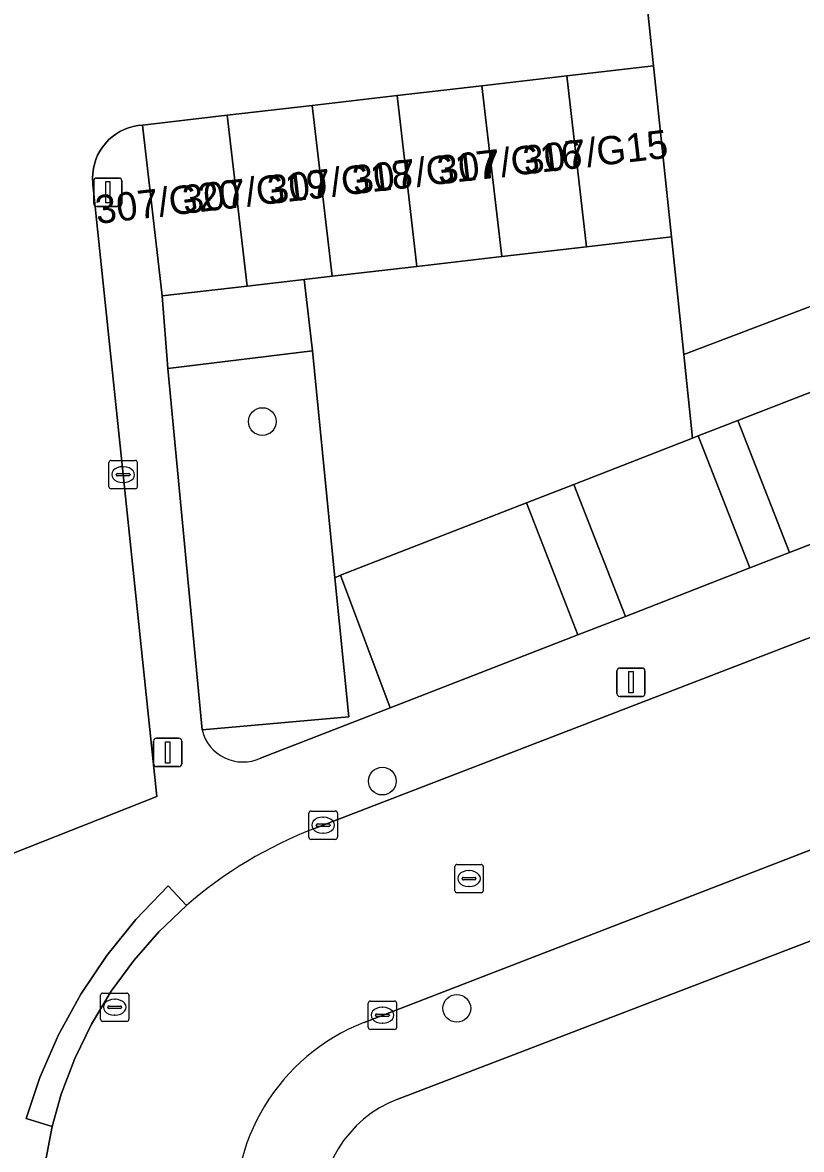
# Model space of a CAD drawing. Extents: x 161248 to 161848, y 384871 to 385383.
# Drawn here: x 161318.63 to 161346.09, y 385275.64 to 385315.39 of the extents above; entities that cross this region are included whole.
import ezdxf

# ---------------------------------------------------------------- set-up
doc = ezdxf.new("R2010")
doc.units = 0
for name, color, linetype in [('IMGEO_Boom', 7, 'Continuous'), ('IMGEO_Erf', 7, 'Continuous'), ('IMGEO_Groenvoorziening', 7, 'Continuous'), ('IMGEO_Kolk', 7, 'Continuous'), ('IMGEO_Lichtmast', 7, 'Continuous'), ('IMGEO_Pand', 7, 'Continuous'), ('IMGEO_Pand_nummerreeks', 7, 'Continuous'), ('IMGEO_Parkeervlak_open', 7, 'Continuous'), ('IMGEO_Rijbaan_lokaal_open', 7, 'Continuous'), ('IMGEO_Rioolput', 7, 'Continuous'), ('IMGEO_Voetpad_open', 7, 'Continuous')]:
    doc.layers.add(name, color=color, linetype=linetype)

msp = doc.modelspace()

# ---------------------------------------------------------------- linework, layer by layer
at = {"layer": 'IMGEO_Boom'}
for centre in [(161327.085, 385301.316), (161331.313, 385288.635), (161333.94, 385280.622)]:
    msp.add_circle(centre, 0.489, dxfattribs=at)
at = {"layer": 'IMGEO_Erf'}
for points in [[(161359.136, 385309.338), (161359.113, 385309.131), (161357.21, 385308.445), (161357.263, 385308.334), (161353.721, 385306.981), (161353.329, 385308.005), (161341.943, 385303.675), (161342.253, 385300.73), (161342.45, 385300.807), (161343.848, 385301.35), (161352.373, 385304.672), (161354.992, 385305.692), (161355.731, 385305.973), (161364.421, 385309.284), (161365.542, 385309.711), (161370.74, 385311.66), (161371.446, 385311.929), (161363.214, 385333.159)], [(161329.169, 385273.002), (161331.681, 385250), (161333.41, 385234.163), (161333.427, 385234.012), (161340.373, 385234.791), (161340.358, 385234.928), (161342.384, 385235.15), (161341.728, 385241.128), (161339.689, 385240.904), (161338.691, 385250), (161338.032, 385256.004), (161341.905, 385256.429), (161341.47, 385260.388), (161341.19, 385260.358), (161340.033, 385270.899), (161354.412, 385272.477), (161354.279, 385273.691), (161354.916, 385273.761), (161354.019, 385285.915), (161331.859, 385277.42)]]:
    msp.add_lwpolyline(points, dxfattribs=at)
msp.add_arc((161333.382, 385273.465), 4.239, 111.0615, 186.2663, dxfattribs=at)
at = {"layer": 'IMGEO_Groenvoorziening'}
msp.add_lwpolyline([(161341.943, 385303.675), (161341.506, 385307.829), (161338.515, 385307.482), (161335.523, 385307.135), (161332.532, 385306.788), (161329.54, 385306.441), (161328.561, 385306.327), (161328.853, 385303.808), (161329.644, 385295.807), (161329.842, 385295.895), (161336.393, 385298.447), (161338.07, 385299.1), (161342.253, 385300.73)], close=True, dxfattribs=at)
at = {"layer": 'IMGEO_Kolk'}
for p, q in [((161321.752, 385299.943), (161322.604, 385299.943)), ((161321.677, 385299.017), (161321.677, 385299.869)), ((161321.979, 385299.486), (161322.377, 385299.486)), ((161322.165, 385299.723), (161322.19, 385299.723)), ((161322.678, 385299.869), (161322.678, 385299.017)), ((161321.936, 385299.437), (161321.936, 385299.449)), ((161322.374, 385299.4), (161321.976, 385299.4)), ((161322.188, 385299.163), (161322.163, 385299.163)), ((161322.42, 385299.449), (161322.42, 385299.437)), ((161322.604, 385298.943), (161321.752, 385298.943)), ((161328.802, 385287.58), (161329.654, 385287.58)), ((161328.727, 385286.654), (161328.727, 385287.506)), ((161329.215, 385287.36), (161329.24, 385287.36)), ((161329.728, 385287.506), (161329.728, 385286.654)), ((161328.986, 385287.074), (161328.986, 385287.086)), ((161329.424, 385287.037), (161329.026, 385287.037)), ((161329.029, 385287.123), (161329.427, 385287.123)), ((161329.238, 385286.8), (161329.213, 385286.8)), ((161329.47, 385287.086), (161329.47, 385287.074)), ((161329.654, 385286.58), (161328.802, 385286.58)), ((161330.818, 385279.952), (161330.818, 385280.804)), ((161330.893, 385280.878), (161331.745, 385280.878)), ((161331.819, 385280.804), (161331.819, 385279.952)), ((161331.12, 385280.421), (161331.518, 385280.421)), ((161331.306, 385280.658), (161331.331, 385280.658)), ((161331.077, 385280.372), (161331.077, 385280.384)), ((161331.515, 385280.335), (161331.117, 385280.335)), ((161331.329, 385280.098), (161331.304, 385280.098)), ((161331.561, 385280.384), (161331.561, 385280.372)), ((161331.745, 385279.878), (161330.893, 385279.878))]:
    msp.add_line(p, q, dxfattribs=at)
for points in [[(161321.752, 385299.943), (161322.604, 385299.943)], [(161321.677, 385299.017), (161321.677, 385299.869)], [(161322.678, 385299.869), (161322.678, 385299.017)], [(161322.604, 385298.943), (161321.752, 385298.943)], [(161328.802, 385287.58), (161329.654, 385287.58)], [(161328.727, 385286.654), (161328.727, 385287.506)], [(161329.728, 385287.506), (161329.728, 385286.654)], [(161329.654, 385286.58), (161328.802, 385286.58)], [(161330.818, 385279.952), (161330.818, 385280.804)], [(161330.893, 385280.878), (161331.745, 385280.878)], [(161331.819, 385280.804), (161331.819, 385279.952)], [(161331.745, 385279.878), (161330.893, 385279.878)]]:
    msp.add_lwpolyline(points, dxfattribs=at)
for centre, radius, start, end in [((161321.754, 385299.867), 0.0765, 91.552, 178.448), ((161321.754, 385299.867), 0.0765, 91.552, 178.448), ((161322.602, 385299.867), 0.0765, 1.552, 88.448), ((161322.602, 385299.867), 0.0765, 1.552, 88.448), ((161321.976, 385299.446), 0.0403, 85.8775, 175.7526), ((161322.381, 385299.448), 0.0386, 1.7309, 96.639), ((161321.973, 385299.436), 0.0366, 178.938, 274.7102), ((161322.377, 385299.443), 0.043, 264.8664, 352.4533), ((161321.754, 385299.019), 0.0765, 181.552, 268.448), ((161321.754, 385299.019), 0.0765, 181.552, 268.448), ((161322.602, 385299.019), 0.0765, 271.552, 358.448), ((161322.602, 385299.019), 0.0765, 271.552, 358.448), ((161328.804, 385287.504), 0.0765, 91.552, 178.448), ((161328.804, 385287.504), 0.0765, 91.552, 178.448), ((161329.652, 385287.504), 0.0765, 1.552, 88.448), ((161329.652, 385287.504), 0.0765, 1.552, 88.448), ((161329.026, 385287.083), 0.0403, 85.8775, 175.7526), ((161329.023, 385287.073), 0.0366, 178.938, 274.7102), ((161329.427, 385287.08), 0.043, 264.8664, 352.4533), ((161329.431, 385287.085), 0.0386, 1.7309, 96.639), ((161328.804, 385286.656), 0.0765, 181.552, 268.448), ((161328.804, 385286.656), 0.0765, 181.552, 268.448), ((161329.652, 385286.656), 0.0765, 271.552, 358.448), ((161329.652, 385286.656), 0.0765, 271.552, 358.448), ((161330.895, 385280.802), 0.0765, 91.552, 178.448), ((161330.895, 385280.802), 0.0765, 91.552, 178.448), ((161331.743, 385280.802), 0.0765, 1.552, 88.448), ((161331.743, 385280.802), 0.0765, 1.552, 88.448), ((161331.117, 385280.381), 0.0403, 85.8775, 175.7526), ((161331.522, 385280.383), 0.0386, 1.7309, 96.639), ((161331.114, 385280.371), 0.0366, 178.938, 274.7102), ((161331.518, 385280.378), 0.043, 264.8664, 352.4533), ((161330.895, 385279.954), 0.0765, 181.552, 268.448), ((161330.895, 385279.954), 0.0765, 181.552, 268.448), ((161331.743, 385279.954), 0.0765, 271.552, 358.448), ((161331.743, 385279.954), 0.0765, 271.552, 358.448)]:
    msp.add_arc(centre, radius, start, end, dxfattribs=at)
for centre, major_axis, ratio, start_param, end_param in [((161322.164, 385299.443), (-0.387, 0.002), 0.722429, 4.712389, 7.853982), ((161322.189, 385299.443), (-0.39, 0.002), 0.717154, 1.570796, 4.712389), ((161329.214, 385287.08), (-0.387, 0.002), 0.722429, 4.712389, 7.853982), ((161329.239, 385287.08), (-0.39, 0.002), 0.717154, 1.570796, 4.712389), ((161331.305, 385280.378), (-0.387, 0.002), 0.722429, 4.712389, 7.853982), ((161331.33, 385280.378), (-0.39, 0.002), 0.717154, 1.570796, 4.712389)]:
    msp.add_ellipse(centre, major_axis=major_axis, ratio=ratio, start_param=start_param, end_param=end_param, dxfattribs=at)
at = {"layer": 'IMGEO_Lichtmast'}
for p, q in [((161321.242, 385309.905), (161322.032, 385309.905)), ((161322.032, 385309.905), (161321.242, 385309.905)), ((161321.142, 385309.005), (161321.142, 385309.805)), ((161321.142, 385309.805), (161321.142, 385309.005)), ((161322.132, 385309.805), (161322.132, 385309.005)), ((161322.132, 385309.005), (161322.132, 385309.805)), ((161322.032, 385308.905), (161321.242, 385308.905)), ((161321.242, 385308.905), (161322.032, 385308.905)), ((161339.581, 385291.722), (161339.581, 385292.522)), ((161339.581, 385292.522), (161339.581, 385291.722)), ((161339.681, 385292.622), (161340.471, 385292.622)), ((161340.471, 385292.622), (161339.681, 385292.622)), ((161340.571, 385292.522), (161340.571, 385291.722)), ((161340.571, 385291.722), (161340.571, 385292.522)), ((161340.471, 385291.622), (161339.681, 385291.622)), ((161339.681, 385291.622), (161340.471, 385291.622)), ((161323.252, 385289.248), (161323.252, 385290.048)), ((161323.252, 385290.048), (161323.252, 385289.248)), ((161323.352, 385290.148), (161324.142, 385290.148)), ((161324.142, 385290.148), (161323.352, 385290.148)), ((161324.242, 385290.048), (161324.242, 385289.248)), ((161324.242, 385289.248), (161324.242, 385290.048)), ((161324.142, 385289.148), (161323.352, 385289.148)), ((161323.352, 385289.148), (161324.142, 385289.148))]:
    msp.add_line(p, q, dxfattribs=at)
for points in [[(161321.562, 385309.78), (161321.712, 385309.78), (161321.712, 385309.03), (161321.562, 385309.03), (161321.562, 385309.78)], [(161340.001, 385292.497), (161340.151, 385292.497), (161340.151, 385291.747), (161340.001, 385291.747), (161340.001, 385292.497)], [(161323.672, 385290.023), (161323.822, 385290.023), (161323.822, 385289.273), (161323.672, 385289.273), (161323.672, 385290.023)]]:
    msp.add_lwpolyline(points, dxfattribs=at)
for centre, start, end in [((161321.242, 385309.805), 90, 180), ((161321.242, 385309.805), 90, 180), ((161322.032, 385309.805), 0, 90), ((161322.032, 385309.805), 360, 90), ((161321.242, 385309.005), 180, 270), ((161321.242, 385309.005), 180, 270), ((161322.032, 385309.005), 270, 0), ((161322.032, 385309.005), 270, 0), ((161339.681, 385292.522), 90, 180), ((161339.681, 385292.522), 90, 180), ((161340.471, 385292.522), 0, 90), ((161340.471, 385292.522), 360, 90), ((161339.681, 385291.722), 180, 270), ((161339.681, 385291.722), 180, 270), ((161340.471, 385291.722), 270, 0), ((161340.471, 385291.722), 270, 0), ((161323.352, 385290.048), 90, 180), ((161323.352, 385290.048), 90, 180), ((161324.142, 385290.048), 0, 90), ((161324.142, 385290.048), 360, 90), ((161323.352, 385289.248), 180, 270), ((161323.352, 385289.248), 180, 270), ((161324.142, 385289.248), 270, 0), ((161324.142, 385289.248), 270, 0)]:
    msp.add_arc(centre, 0.1, start, end, dxfattribs=at)
at = {"layer": 'IMGEO_Pand'}
msp.add_lwpolyline([(161364.248, 385315.991), (161365.668, 385316.057), (161365.156, 385326.33), (161363.758, 385326.266), (161363.523, 385331.042), (161339.195, 385329.807), (161339.824, 385323.814), (161340.871, 385313.86), (161341.506, 385307.829), (161341.943, 385303.675), (161353.329, 385308.005), (161353.721, 385306.981), (161357.263, 385308.334), (161357.21, 385308.445), (161359.113, 385309.131), (161359.136, 385309.338)], dxfattribs=at)
for points in [[(161338.515, 385307.482), (161341.506, 385307.829), (161340.871, 385313.86), (161337.816, 385313.505)], [(161335.523, 385307.135), (161338.515, 385307.482), (161337.816, 385313.505), (161334.824, 385313.158)], [(161334.824, 385313.158), (161331.833, 385312.811), (161332.532, 385306.788), (161335.523, 385307.135)], [(161329.54, 385306.441), (161332.532, 385306.788), (161331.833, 385312.811), (161328.841, 385312.464)], [(161328.561, 385306.327), (161329.54, 385306.441), (161328.841, 385312.464), (161325.85, 385312.117), (161326.548, 385306.094)], [(161322.859, 385311.77), (161323.557, 385305.747), (161326.548, 385306.094), (161325.85, 385312.117)]]:
    msp.add_lwpolyline(points, close=True, dxfattribs=at)
at = {"layer": 'IMGEO_Parkeervlak_open'}
for points in [[(161354.187, 385300.016), (161352.373, 385304.672), (161343.848, 385301.35), (161345.661, 385296.695)], [(161328.853, 385303.808), (161323.752, 385303.182), (161324.958, 385290.439), (161330.129, 385290.905), (161329.644, 385295.807)], [(161339.883, 385294.445), (161344.263, 385296.151), (161342.45, 385300.807), (161342.253, 385300.73), (161338.07, 385299.1)], [(161336.393, 385298.447), (161329.842, 385295.895), (161331.59, 385291.215), (161338.206, 385293.792)]]:
    msp.add_lwpolyline(points, close=True, dxfattribs=at)
at = {"layer": 'IMGEO_Rijbaan_lokaal_open'}
for points in [[(161317.793, 385285.896), (161323.36, 385288.088), (161321.115, 385309.674), (161321.108, 385309.737), (161321.1, 385309.904), (161321.106, 385310.07), (161321.128, 385310.235), (161321.164, 385310.397), (161321.215, 385310.556), (161321.279, 385310.709), (161321.357, 385310.856), (161321.448, 385310.996), (161321.551, 385311.127), (161321.665, 385311.248), (161321.789, 385311.358), (161321.923, 385311.457), (161322.065, 385311.543), (161322.215, 385311.617), (161322.37, 385311.677), (161322.53, 385311.722), (161322.693, 385311.754), (161322.859, 385311.77), (161325.85, 385312.117), (161328.841, 385312.464), (161331.833, 385312.811), (161334.824, 385313.158), (161337.816, 385313.505), (161340.871, 385313.86), (161339.824, 385323.814)], [(161385.091, 385308.618), (161379.805, 385306.58), (161374.2, 385304.421), (161328.923, 385286.962)], [(161330.668, 385280.124), (161356.419, 385290.084), (161372.709, 385296.384), (161387.128, 385301.961)], [(161324.411, 385284.249), (161323.437, 385283.32), (161322.549, 385282.308), (161321.756, 385281.221), (161321.063, 385280.067), (161320.475, 385278.856), (161319.999, 385277.598), (161319.678, 385276.452), (161319.391, 385274.978), (161319.265, 385273.638), (161319.259, 385272.292), (161319.33, 385271.321), (161321.575, 385250), (161326.822, 385201.971), (161327.141, 385199.049)]]:
    msp.add_lwpolyline(points, dxfattribs=at)
for centre, radius, start, end in [((161334.322, 385272.875), 15.087, 110.9691, 131.0667), ((161333.288, 385273.455), 7.166, 111.4479, 186.0931)]:
    msp.add_arc(centre, radius, start, end, dxfattribs=at)
at = {"layer": 'IMGEO_Rioolput'}
for p, q in [((161333.871, 385284.771), (161333.871, 385285.623)), ((161333.946, 385285.697), (161334.798, 385285.697)), ((161334.872, 385285.623), (161334.872, 385284.771)), ((161334.13, 385285.191), (161334.13, 385285.203)), ((161334.173, 385285.24), (161334.571, 385285.24)), ((161334.359, 385285.477), (161334.384, 385285.477)), ((161334.614, 385285.203), (161334.614, 385285.191)), ((161334.568, 385285.154), (161334.17, 385285.154)), ((161334.382, 385284.917), (161334.357, 385284.917)), ((161334.798, 385284.697), (161333.946, 385284.697)), ((161321.38, 385280.234), (161321.38, 385281.086)), ((161321.455, 385281.16), (161322.307, 385281.16)), ((161321.868, 385280.94), (161321.893, 385280.94)), ((161322.381, 385281.086), (161322.381, 385280.234)), ((161321.639, 385280.654), (161321.639, 385280.666)), ((161322.077, 385280.617), (161321.679, 385280.617)), ((161321.682, 385280.703), (161322.08, 385280.703)), ((161322.123, 385280.666), (161322.123, 385280.654)), ((161322.307, 385280.16), (161321.455, 385280.16)), ((161321.891, 385280.38), (161321.866, 385280.38))]:
    msp.add_line(p, q, dxfattribs=at)
for points in [[(161333.871, 385284.771), (161333.871, 385285.623)], [(161333.946, 385285.697), (161334.798, 385285.697)], [(161334.872, 385285.623), (161334.872, 385284.771)], [(161334.798, 385284.697), (161333.946, 385284.697)], [(161321.38, 385280.234), (161321.38, 385281.086)], [(161321.455, 385281.16), (161322.307, 385281.16)], [(161322.381, 385281.086), (161322.381, 385280.234)], [(161322.307, 385280.16), (161321.455, 385280.16)]]:
    msp.add_lwpolyline(points, dxfattribs=at)
for centre, radius, start, end in [((161333.948, 385285.621), 0.0765, 91.552, 178.448), ((161333.948, 385285.621), 0.0765, 91.552, 178.448), ((161334.796, 385285.621), 0.0765, 1.552, 88.448), ((161334.796, 385285.621), 0.0765, 1.552, 88.448), ((161334.17, 385285.2), 0.0403, 85.8775, 175.7526), ((161334.167, 385285.19), 0.0366, 178.938, 274.7102), ((161334.571, 385285.197), 0.043, 264.8664, 352.4533), ((161334.575, 385285.202), 0.0386, 1.7309, 96.639), ((161333.948, 385284.773), 0.0765, 181.552, 268.448), ((161333.948, 385284.773), 0.0765, 181.552, 268.448), ((161334.796, 385284.773), 0.0765, 271.552, 358.448), ((161334.796, 385284.773), 0.0765, 271.552, 358.448), ((161321.457, 385281.084), 0.0765, 91.552, 178.448), ((161321.457, 385281.084), 0.0765, 91.552, 178.448), ((161322.305, 385281.084), 0.0765, 1.552, 88.448), ((161322.305, 385281.084), 0.0765, 1.552, 88.448), ((161321.679, 385280.663), 0.0403, 85.8775, 175.7526), ((161321.676, 385280.653), 0.0366, 178.938, 274.7102), ((161322.08, 385280.66), 0.043, 264.8664, 352.4533), ((161322.084, 385280.665), 0.0386, 1.7309, 96.639), ((161321.457, 385280.236), 0.0765, 181.552, 268.448), ((161321.457, 385280.236), 0.0765, 181.552, 268.448), ((161322.305, 385280.236), 0.0765, 271.552, 358.448), ((161322.305, 385280.236), 0.0765, 271.552, 358.448)]:
    msp.add_arc(centre, radius, start, end, dxfattribs=at)
for centre, major_axis, ratio, start_param, end_param in [((161334.358, 385285.197), (-0.387, 0.002), 0.722429, 4.712389, 7.853982), ((161334.383, 385285.197), (-0.39, 0.002), 0.717154, 1.570796, 4.712389), ((161321.867, 385280.66), (-0.387, 0.002), 0.722429, 4.712389, 7.853982), ((161321.892, 385280.66), (-0.39, 0.002), 0.717154, 1.570796, 4.712389)]:
    msp.add_ellipse(centre, major_axis=major_axis, ratio=ratio, start_param=start_param, end_param=end_param, dxfattribs=at)
at = {"layer": 'IMGEO_Voetpad_open'}
for points in [[(161324.958, 385290.439), (161323.752, 385303.182), (161323.557, 385305.747), (161322.859, 385311.77), (161322.693, 385311.754), (161322.53, 385311.722), (161322.37, 385311.677), (161322.215, 385311.617), (161322.065, 385311.543), (161321.923, 385311.457), (161321.789, 385311.358), (161321.665, 385311.248), (161321.551, 385311.127), (161321.448, 385310.996), (161321.357, 385310.856), (161321.279, 385310.709), (161321.215, 385310.556), (161321.164, 385310.397), (161321.128, 385310.235), (161321.106, 385310.07), (161321.1, 385309.904), (161321.108, 385309.737), (161321.115, 385309.674), (161323.36, 385288.088), (161317.793, 385285.896)], [(161384.338, 385311.736), (161381.442, 385310.439), (161379.264, 385309.606), (161378.562, 385309.338), (161373.246, 385307.287), (161372.572, 385307.047), (161367.354, 385305.061), (161366.235, 385304.625), (161357.541, 385301.323), (161354.187, 385300.016), (161345.661, 385296.695), (161344.263, 385296.151), (161339.883, 385294.445), (161338.206, 385293.792), (161331.59, 385291.215), (161327.022, 385289.445)], [(161328.923, 385286.962), (161374.2, 385304.421), (161379.805, 385306.58), (161385.091, 385308.618)], [(161387.128, 385301.961), (161372.709, 385296.384), (161373.148, 385295.252), (161356.865, 385288.934), (161356.419, 385290.084), (161330.668, 385280.124)], [(161331.859, 385277.42), (161354.019, 385285.915), (161357.516, 385287.256), (161373.799, 385293.574), (161391.455, 385300.374), (161398.96, 385300.934)], [(161327.022, 385289.445), (161331.59, 385291.215), (161329.842, 385295.895), (161329.644, 385295.807), (161330.129, 385290.905), (161324.958, 385290.439)], [(161312.135, 385161.71), (161328.129, 385163.466), (161330.574, 385163.733), (161326.646, 385198.993), (161327.141, 385199.049), (161326.822, 385201.971), (161321.575, 385250), (161319.33, 385271.321), (161319.259, 385272.292), (161319.265, 385273.638), (161319.391, 385274.978), (161319.678, 385276.452), (161318.759, 385276.732), (161319.247, 385278.182), (161319.902, 385279.684), (161320.689, 385281.122), (161321.6, 385282.484), (161322.63, 385283.759), (161323.77, 385284.937), (161324.411, 385284.249)]]:
    msp.add_lwpolyline(points, dxfattribs=at)
for points in [[(161326.548, 385306.094), (161323.557, 385305.747), (161323.752, 385303.182), (161328.853, 385303.808), (161328.561, 385306.327)], [(161345.661, 385296.695), (161343.848, 385301.35), (161342.45, 385300.807), (161344.263, 385296.151)], [(161338.07, 385299.1), (161336.393, 385298.447), (161338.206, 385293.792), (161339.883, 385294.445)], [(161322.549, 385282.308), (161323.437, 385283.32), (161324.411, 385284.249), (161323.77, 385284.937), (161322.63, 385283.759), (161321.6, 385282.484), (161320.689, 385281.122), (161319.902, 385279.684), (161319.247, 385278.182), (161318.759, 385276.732), (161319.678, 385276.452), (161319.999, 385277.598), (161320.475, 385278.856), (161321.063, 385280.067), (161321.756, 385281.221)]]:
    msp.add_lwpolyline(points, close=True, dxfattribs=at)
for centre, radius, start, end in [((161326.403, 385290.8), 1.49, 194.0358, 294.5343), ((161326.403, 385290.8), 1.49, 194.0358, 294.5343), ((161334.322, 385272.875), 15.087, 110.9691, 131.0667), ((161333.288, 385273.455), 7.166, 111.4479, 186.0931), ((161333.382, 385273.465), 4.239, 111.0615, 186.2663)]:
    msp.add_arc(centre, radius, start, end, dxfattribs=at)

# ---------------------------------------------------------------- texts
at = {"layer": 'IMGEO_Pand_nummerreeks'}
for s, p in [('307/G15', (161336.333, 385310.031)), ('307/G16', (161333.31, 385309.681)), ('307/G17', (161330.318, 385309.334)), ('307/G18', (161327.33, 385308.987)), ('307/G20', (161321.257, 385308.282)), ('307/G19', (161324.332, 385308.639))]:
    msp.add_text(s, height=1, rotation=6.6186, dxfattribs=at).set_placement(p)

doc.saveas('drawing.dxf')
